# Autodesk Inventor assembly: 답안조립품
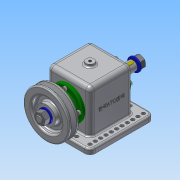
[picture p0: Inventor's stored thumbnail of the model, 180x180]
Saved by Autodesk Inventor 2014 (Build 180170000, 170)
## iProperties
Created: 2018-11
Part Number: 답안조립품
Document SubType Name: Assembly
Designer: Administrator
Author: Administrator
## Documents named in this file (13)
- C:\Users\Administrator\Desktop\481107V1028\답안조립품.iam
- C:\Users\Administrator\Desktop\481107V1028\본체.ipt
- C:\Users\Administrator\Desktop\481107V1028\V벨트풀리.ipt
- C:\Users\Administrator\Desktop\481107V1028\너트 M12x1.25.ipt
- C:\Users\Administrator\Desktop\481107V1028\베어링 6203.ipt
- C:\Users\Administrator\Desktop\481107V1028\볼트 M4.ipt
- C:\Users\Administrator\Desktop\481107V1028\부시.ipt
- C:\Users\Administrator\Desktop\481107V1028\스퍼기어.ipt
- C:\Users\Administrator\Desktop\481107V1028\오일 실 26 38 8.ipt
- C:\Users\Administrator\Desktop\481107V1028\와셔 12x24.ipt
- C:\Users\Administrator\Desktop\481107V1028\축.ipt
- C:\Users\Administrator\Desktop\481107V1028\커버.ipt
- C:\Users\Administrator\Desktop\481107V1028\키 5x5x12.ipt
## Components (1 placed, 1 different names)
1. V벨트풀리:1 — 각도:3
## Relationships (1: Angle 1)
- 각도:3 [Angle]: V벨트풀리:1
